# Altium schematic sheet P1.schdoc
size 594 x 419 mm; Symbol: Drawing-Symbol_A4; @Project Name: WYVERN-E; @Page Count: 1; @Update Date: 2026-08-05; @Create Date: 2026-08-05; @Schematic Name: Schematic1; @Page No: 1; @Page Name: P1; Company: EasyEDA.com; Version: V1.0; Page Size: A2; Device: Drawing-Symbol_A4; @Create Time: 14:42:15; @Update Time: 14:42:15; Border: 1; Width: 2338; Height: 1652; Region Start: 1; X Region Count: 6; Y Region Count: 4; Blade Width: 10; Title Block Position: 3; @Board Name: Board1
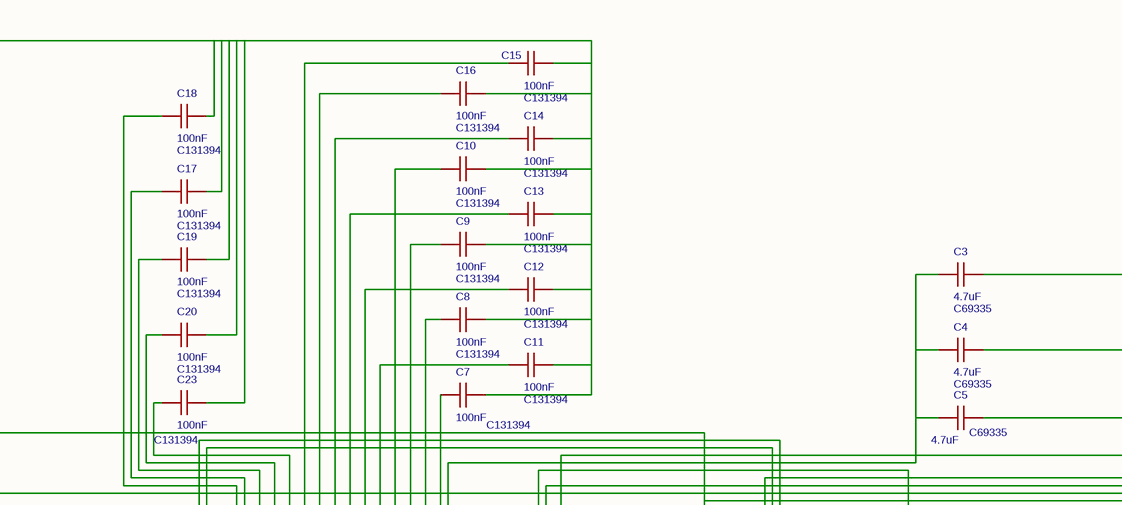
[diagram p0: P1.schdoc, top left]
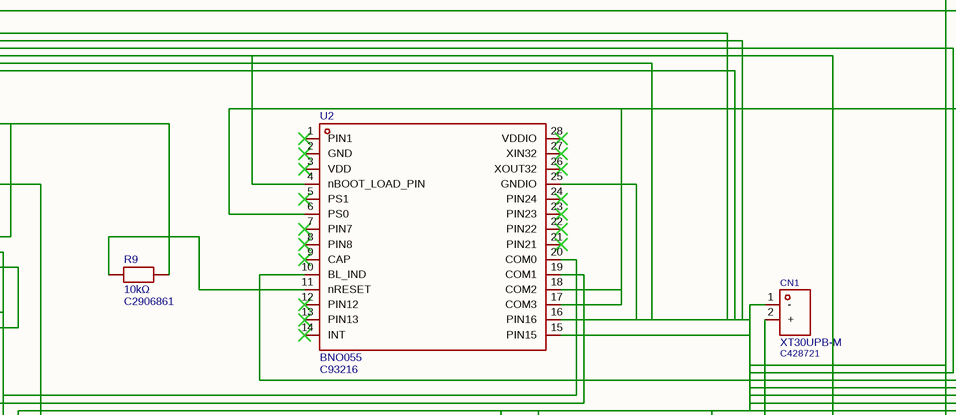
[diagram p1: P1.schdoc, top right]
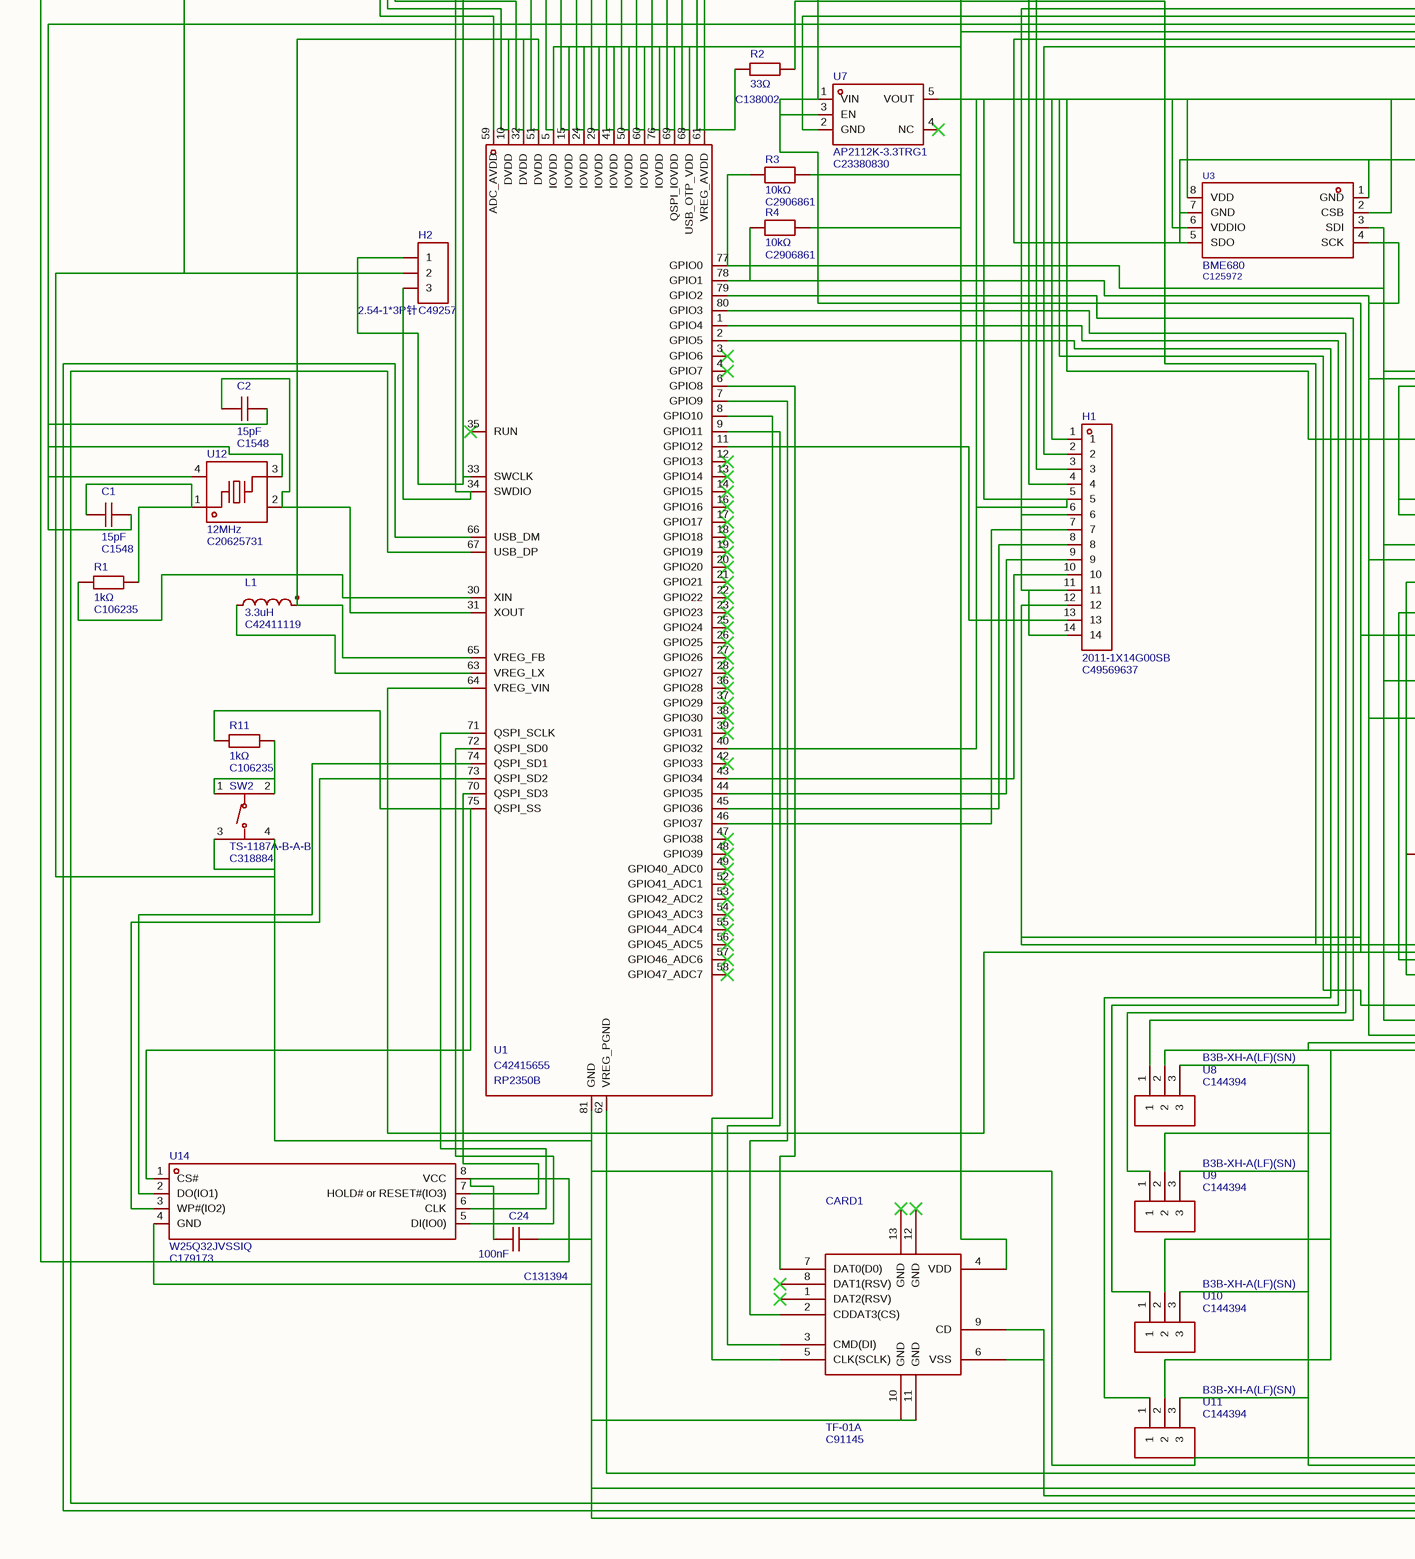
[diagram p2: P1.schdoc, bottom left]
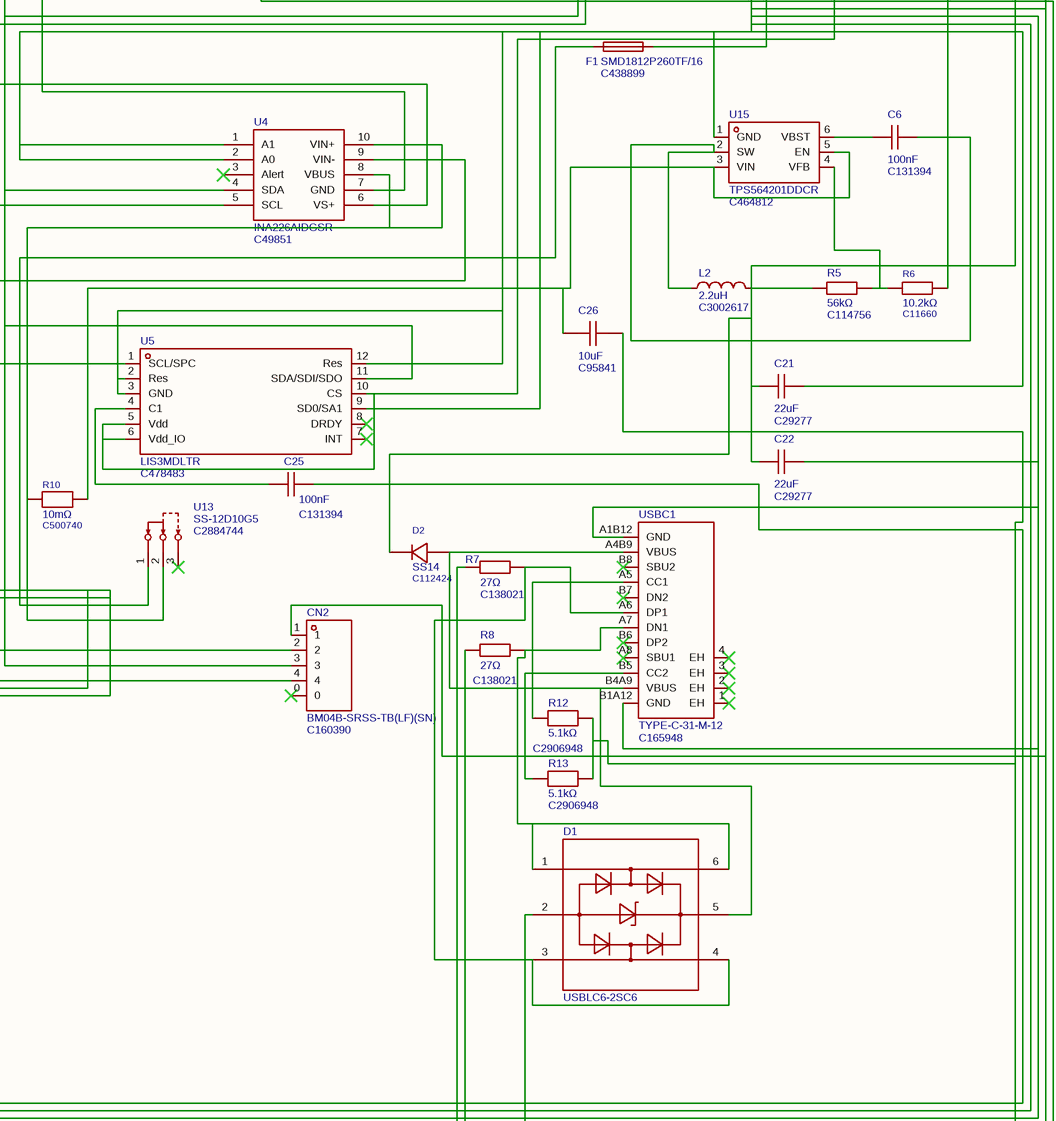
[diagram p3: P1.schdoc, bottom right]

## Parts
C1  15pF  Supplier Part: C1548  [C0402]
C2  15pF  Supplier Part: C1548  [C0402]
C3  4.7uF  Supplier Part: C69335  [C0603]
C4  4.7uF  Supplier Part: C69335  [C0603]
C5  4.7uF  Supplier Part: C69335  [C0603]
C6  100nF  Supplier Part: C131394  [C0402]
C7  100nF  Supplier Part: C131394  [C0402]
C8  100nF  Supplier Part: C131394  [C0402]
C9  100nF  Supplier Part: C131394  [C0402]
C10  100nF  Supplier Part: C131394  [C0402]
C11  100nF  Supplier Part: C131394  [C0402]
C12  100nF  Supplier Part: C131394  [C0402]
C13  100nF  Supplier Part: C131394  [C0402]
C14  100nF  Supplier Part: C131394  [C0402]
C15  100nF  Supplier Part: C131394  [C0402]
C16  100nF  Supplier Part: C131394  [C0402]
C17  100nF  Supplier Part: C131394  [C0402]
C18  100nF  Supplier Part: C131394  [C0402]
C19  100nF  Supplier Part: C131394  [C0402]
C20  100nF  Supplier Part: C131394  [C0402]
C21  22uF  Supplier Part: C29277  [C0805]
C22  22uF  Supplier Part: C29277  [C0805]
C23  100nF  Supplier Part: C131394  [C0402]
C24  100nF  Supplier Part: C131394  [C0402]
C25  100nF  Supplier Part: C131394  [C0402]
C26  10uF  Supplier Part: C95841  [C0805]
CARD1  TF-01A  Supplier Part: C91145  [TF-SMD_TF-01A]
CN1  XT30UPB-M  Supplier Part: C428721  [CONN-TH_XT30UPB-M]
CN2  BM04B-SRSS-TB(LF)(SN)  Supplier Part: C160390  [CONN-SMD_BM04B-SRSS-TB]
D1  USBLC6-2SC6  [SOT-23-6_L2.9-W1.6-P0.95-LS2.8-BL]
D2  SS14  Supplier Part: C112424  [SMA_L4.4-W2.6-LS5.0-RD]
F1  SMD1812P260TF/16  Supplier Part: C438899  [F1812]
H1  2011-1X14G00SB  Supplier Part: C49569637  [HDR-TH_14P-P2.54-V-M_4]
H2  2.54-1*3P针  Supplier Part: C49257  [HDR-TH_3P-P2.54-V-M-1]
L1  3.3uH  Supplier Part: C42411119  [IND-SMD_L2.0-W1.6_AOTA-B201610S3R3-101-T]
L2  2.2uH  Supplier Part: C3002617  [IND-SMD_L5.7-W5.1]
R1  1kΩ  Supplier Part: C106235  [R0402]
R2  33Ω  Supplier Part: C138002  [R0402]
R3  10kΩ  Supplier Part: C2906861  [R0402]
R4  10kΩ  Supplier Part: C2906861  [R0402]
R5  56kΩ  Supplier Part: C114756  [R0402]
R6  10.2kΩ  Supplier Part: C11660  [R0402]
R7  27Ω  Supplier Part: C138021  [R0402]
R8  27Ω  Supplier Part: C138021  [R0402]
R9  10kΩ  Supplier Part: C2906861  [R0402]
R10  10mΩ  Supplier Part: C500740  [R2512]
R11  1kΩ  Supplier Part: C106235  [R0402]
R12  5.1kΩ  Supplier Part: C2906948  [R0402]
R13  5.1kΩ  Supplier Part: C2906948  [R0402]
SW2  TS-1187A-B-A-B  Supplier Part: C318884  [SW-SMD_4P-L5.1-W5.1-P3.70-LS6.5-TL_H1.5]
U1  RP2350B  Supplier Part: C42415655  [QFN-80_L10.0-W10.0-P0.40-TL-EP3.4]
U2  BNO055  Supplier Part: C93216  [LGA-28_L5.2-W3.8-P0.50-BL]
U3  BME680  Supplier Part: C125972  [LGA-8_L3.0-W3.0-P0.80-TR]
U4  INA226AIDGSR  Supplier Part: C49851  [MSOP-10_L3.0-W3.0-P0.50-LS5.0-BL]
U5  LIS3MDLTR  Supplier Part: C478483  [LGA-12_L2.0-W2.0-P0.50-BL]
U7  AP2112K-3.3TRG1  Supplier Part: C23380830  [SOT-23-5_L2.9-W1.6-P0.95-LS2.8-BR]
U8  B3B-XH-A(LF)(SN)  Supplier Part: C144394  [CONN-TH_3P-P2.50_A2501WV2-3P]
U9  B3B-XH-A(LF)(SN)  Supplier Part: C144394  [CONN-TH_3P-P2.50_A2501WV2-3P]
U10  B3B-XH-A(LF)(SN)  Supplier Part: C144394  [CONN-TH_3P-P2.50_A2501WV2-3P]
U11  B3B-XH-A(LF)(SN)  Supplier Part: C144394  [CONN-TH_3P-P2.50_A2501WV2-3P]
U12  12MHz  Supplier Part: C20625731  [CRYSTAL-SMD_4P-L3.2-W2.5-BL]
U13  SS-12D10G5  Supplier Part: C2884744  [SW-TH_SS-12D10L9]
U14  W25Q32JVSSIQ  Supplier Part: C179173  [SOIC-8_L5.3-W5.3-P1.27-LS8.0-BL]
U15  TPS564201DDCR  Supplier Part: C464812  [SOT-23-6_L2.9-W1.6-P0.95-LS2.8-BL]
USBC1  TYPE-C-31-M-12  Supplier Part: C165948  [USB-C_SMD-TYPE-C-31-M-12_1]

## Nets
NetC1_1: C1.1 R1.2 U12.1
NetC1_2: C1.2 C2.2 C3.2 C4.2 C5.2 C7.2 C8.2 C9.2 C10.2 C11.2 C12.2 C13.2 C14.2 C15.2 C16.2 C17.2 C18.2 C19.2 C20.2 C21.2 C22.2 C23.2 C24.2 C25.2 C26.2 CARD1.6(VSS) CARD1.9(CD) CARD1.10(GND) CARD1.11(GND) CN1.1(-) CN2.1 D1.2 H1.2 H1.6 H1.11 H1.14 H2.2 R6.2 R12.2 R13.2 SW2.3(C) SW2.4(D) U1.62(VREG_PGND) U1.81(GND) U2.6(PS0) U2.10(BL_IND) U2.15(PIN15) U2.16(PIN16) U2.17(COM3) U2.18(COM2) U2.25(GNDIO) U3.1(GND) U3.5(SDO) U3.7(GND) U4.1(A1) U4.2(A0) U4.7(GND) U5.2(Res) U5.3(GND) U5.9(SD0/SA1) U5.12(Res) U7.2(GND) U8.3 U9.3 U10.3 U11.3 U12.3 U12.4(GND) U14.4(GND) U15.1(GND) USBC1.A1B12(GND) USBC1.B1A12(GND)
NetC2_1: C2.1 U1.31(XOUT) U12.2(GND)
NetC3_1: C3.1 C4.1 C5.1 C7.1 R2.1 U1.61(VREG_AVDD)
NetC6_1: C6.1 U15.6(VBST)
NetC6_2: C6.2 L2.1 U15.2(SW)
NetC8_1: C8.1 C9.1 C10.1 C11.1 C12.1 C13.1 C14.1 C15.1 C16.1 C23.1 C24.1 CARD1.4(VDD) CN2.2 H1.1 H1.5 R3.2 R4.2 R9.2 U1.5(IOVDD) U1.15(IOVDD) U1.24(IOVDD) U1.29(IOVDD) U1.40(GPIO32) U1.41(IOVDD) U1.50(IOVDD) U1.60(IOVDD) U1.68(USB_OTP_VDD) U1.69(QSPI_IOVDD) U1.76(IOVDD) U2.4(nBOOT_LOAD_PIN) U3.2(CSB) U3.6(VDDIO) U3.8(VDD) U4.6(VS+) U5.5(Vdd) U5.6(Vdd_IO) U5.10(CS) U7.5(VOUT) U14.8(VCC)
NetC17_1: C17.1 C19.1 C20.1 L1.2 U1.10(DVDD) U1.32(DVDD) U1.51(DVDD) U1.65(VREG_FB)
NetC18_1: C18.1 U1.59(ADC_AVDD)
NetC21_1: C21.1 C22.1 D2.1(C) H1.12 L2.2 R2.2 R5.1 U1.64(VREG_VIN) U4.9(VIN-) U7.1(VIN) U7.3(EN) U8.2 U9.2 U10.2 U11.2
NetC25_1: C25.1 U5.4(C1)
NetC26_1: C26.1 R10.2 U15.3(VIN) U15.5(EN)
NetCARD1_2: CARD1.2(CDDAT3(CS)) U1.7(GPIO9)
NetCARD1_3: CARD1.3(CMD(DI)) U1.9(GPIO11)
NetCARD1_5: CARD1.5(CLK(SCLK)) U1.8(GPIO10)
NetCARD1_7: CARD1.7(DAT0(D0)) U1.6(GPIO8)
NetCN1_2: CN1.2(+) F1.2
NetCN2_3: CN2.3 R3.1 U1.77(GPIO0) U2.20(COM0) U3.3(SDI) U4.4(SDA) U5.11(SDA/SDI/SDO)
NetCN2_4: CN2.4 R4.1 U1.78(GPIO1) U2.19(COM1) U3.4(SCK) U4.5(SCL) U5.1(SCL/SPC)
NetD1_1: D1.1 D1.6 R8.2 USBC1.A7(DN1)
NetD1_3: D1.3 D1.4 R7.2 USBC1.A6(DP1)
NetD1_5: D1.5 D2.2(A) USBC1.A4B9(VBUS) USBC1.B4A9(VBUS)
NetF1_1: F1.1 U13.1
NetH1_3: H1.3 H2.3 U1.34(SWDIO)
NetH1_4: H1.4 H2.1 U1.33(SWCLK)
NetH1_7: H1.7 U1.46(GPIO37)
NetH1_8: H1.8 U1.45(GPIO36)
NetH1_9: H1.9 U1.44(GPIO35)
NetH1_10: H1.10 U1.43(GPIO34)
NetH1_13: H1.13 U1.11(GPIO12)
NetL1_1: L1.1 U1.63(VREG_LX)
NetR1_1: R1.1 U1.30(XIN)
NetR5_2: R5.2 R6.1 U15.4(VFB)
NetR7_1: R7.1 U1.67(USB_DP)
NetR8_1: R8.1 U1.66(USB_DM)
NetR9_1: R9.1 U2.11(nRESET)
NetR10_1: R10.1 U4.8(VBUS) U4.10(VIN+) U13.2
NetR11_1: R11.1 U1.75(QSPI_SS) U14.1(CS#)
NetR11_2: R11.2 SW2.1(A) SW2.2(B)
NetR12_1: R12.1 USBC1.A5(CC1)
NetR13_1: R13.1 USBC1.B5(CC2)
NetU1_1: U1.1(GPIO4) U10.1
NetU1_2: U1.2(GPIO5) U11.1
NetU1_70: U1.70(QSPI_SD3) U14.7(HOLD#_or_RESET#(IO3))
NetU1_71: U1.71(QSPI_SCLK) U14.6(CLK)
NetU1_72: U1.72(QSPI_SD0) U14.5(DI(IO0))
NetU1_73: U1.73(QSPI_SD2) U14.3(WP#(IO2))
NetU1_74: U1.74(QSPI_SD1) U14.2(DO(IO1))
NetU1_79: U1.79(GPIO2) U8.1
NetU1_80: U1.80(GPIO3) U9.1

Not connected (* = marked no-connect by the designer): CARD1 1(DAT2(RSV))* 8(DAT1(RSV))* 12(GND)* 13(GND)*; CN2 0*; U1 3(GPIO6)* 4(GPIO7)* 12(GPIO13)* 13(GPIO14)* 14(GPIO15)* 16(GPIO16)* 17(GPIO17)* 18(GPIO18)* 19(GPIO19)* 20(GPIO20)* 21(GPIO21)* 22(GPIO22)* 23(GPIO23)* 25(GPIO24)* 26(GPIO25)* 27(GPIO26)* 28(GPIO27)* 35(RUN)* 36(GPIO28)* 37(GPIO29)* 38(GPIO30)* 39(GPIO31)* 42(GPIO33)* 47(GPIO38)* 48(GPIO39)* 49(GPIO40_ADC0)* 52(GPIO41_ADC1)* 53(GPIO42_ADC2)* 54(GPIO43_ADC3)* 55(GPIO44_ADC4)* 56(GPIO45_ADC5)* 57(GPIO46_ADC6)* 58(GPIO47_ADC7)*; U2 1(PIN1)* 2(GND)* 3(VDD)* 5(PS1)* 7(PIN7)* 8(PIN8)* 9(CAP)* 12(PIN12)* 13(PIN13)* 14(INT)* 21(PIN21)* 22(PIN22)* 23(PIN23)* 24(PIN24)* 26(XOUT32)* 27(XIN32)* 28(VDDIO)*; U4 3(Alert)*; U5 7(INT)* 8(DRDY)*; U7 4(NC)*; U13 3*; USBC1 1(EH)* 2(EH)* 3(EH)* 4(EH)* A8(SBU1)* B6(DP2)* B7(DN2)* B8(SBU2)*

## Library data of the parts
C1 C2 = 0402CG150J500NT: Capacitance:15pF Tolerance:±5% Tolerance:±5% Voltage Rating:50V Temperature Coefficient:C0G; Manufacturer: FH(风华); AddInBom: yes; ModelId: b7d13df3e9464d7a99d0651d1a5b4d570819f05c4eef4c71ace90d822a990e87; ModelName: C0402_L1.0-W0.5-H0.5; ModelTransform: 39.37,19.685,0,0,0,0,0,0,0; Tolerance: ±5%; Voltage Rating: 50V; Temperature Coefficient: C0G
C3-C5 = CL10A475KA8NQNC: Capacitance:4.7uF Tolerance:±10% Tolerance:±10% Voltage Rating:25V Temperature Coefficient:X5R; Manufacturer: SAMSUNG(三星); 3D Model: 624118aa3cc7497086c383c2d72e08520819f05c4eef4c71ace90d822a990e87; 3D Model Transform: 62.992,31.496,0,0,0,0,0,0,0; Tolerance: ±10%; Voltage Rating: 25V; Temperature Coefficient: X5R; AddInBom: yes; ModelName: C0603_L1.6-W0.8-H0.8
C6 = CC0402KRX7R9BB104: Capacitance:100nF Tolerance:±10% Tolerance:±10% Voltage Rating:50V Temperature Coefficient:X7R; Manufacturer: YAGEO(国巨); AddInBom: yes; ModelId: b7d13df3e9464d7a99d0651d1a5b4d570819f05c4eef4c71ace90d822a990e87; ModelName: C0402_L1.0-W0.5-H0.5; ModelTransform: 39.37,19.685,0,0,0,0,0,0,0; Tolerance: ±10%; Voltage Rating: 50V; Temperature Coefficient: X7R
C7-C20 C23-C25 = CC0402KRX7R9BB104: Capacitance:100nF Tolerance:±10% Tolerance:±10% Voltage Rating:50V Temperature Coefficient:X7R; Manufacturer: YAGEO(国巨); 3D Model: b7d13df3e9464d7a99d0651d1a5b4d570819f05c4eef4c71ace90d822a990e87; 3D Model Transform: 39.37,19.685,0,0,0,0,0,0,0; Tolerance: ±10%; Voltage Rating: 50V; Temperature Coefficient: X7R; AddInBom: yes; ModelName: C0402_L1.0-W0.5-H0.5
C21 C22 = CL21A226MPQNNNE: Capacitance:22uF Tolerance:±20% Tolerance:±20% Voltage Rating:10V Temperature Coefficient:X5R; Manufacturer: SAMSUNG(三星); AddInBom: yes; ModelId: 8c88e81f49c6409b980720ec8953afb60819f05c4eef4c71ace90d822a990e87; ModelName: C0805_L2.0-W1.3-H1.3; ModelTransform: 78.74,51.181,0,0,0,0,0,0.0005,0; Tolerance: ±20%; Voltage Rating: 10V; Temperature Coefficient: X5R
C26 = CL21B106KOQNNNE: Capacitance:10uF Tolerance:±10% Tolerance:±10% Voltage Rating:16V Temperature Coefficient:X7R; Manufacturer: SAMSUNG(三星); AddInBom: yes; ModelId: 8c88e81f49c6409b980720ec8953afb60819f05c4eef4c71ace90d822a990e87; ModelName: C0805_L2.0-W1.3-H1.3; ModelTransform: 78.74,51.181,0,0,0,0,0,0.0005,0; Tolerance: ±10%; Voltage Rating: 16V; Temperature Coefficient: X7R
CARD1 = TF-01A_C91145: Card Connection Mode:Push-Push Card Type:MicroSD Card (TF Card) Connector Type:Connector and Ejector Additional Card Detection Pins:- Supplementary Features:With Locating Pins Height Above Board:1.85mm Operating Temperature:- Operating Temperature:-; Manufacturer: 韩国韩荣; 3D Model: 5685a23adc9a4e3e9b914abe5ae03aae0819f05c4eef4c71ace90d822a990e87; 3D Model Transform: 633.85696,590.65303,0,0,0,0,0,-85.63,-23.622; AddInBom: yes
CN1 = XT30UPB-M: Rated current:15A Rated voltage: colour:Yellow Connector type:Model aircraft plug contact resistance: interface form:Male insulating material: metal material:Gold plating; Manufacturer: AMASS(艾迈斯); 3D Model: 8606296c6a2a4a0aa30f28b26a2c1e3a0819f05c4eef4c71ace90d822a990e87; 3D Model Transform: 401.574,204.724,0,0,0,0,0,0,-78.74; Rated current: 15A; interface form: Male; AddInBom: yes
CN2 = BM04B-SRSS-TB(LF)(SN): Pins Structure:1x4P Pitch:1mm Mounting Type:Surface Mount,Vertical Reference Series:SR Number of Pins:4P Number of Rows:1 Number of PINs Per Row:4 Row Spacing:- Current Rating:1A Contact Material:Copper alloy Contact Plating:Tin Operating Temperature:-25℃; Manufacturer: JST; AddInBom: yes; ModelId: c8b0a6165d564a1890ab3ee4bf911cf30819f05c4eef4c71ace90d822a990e87; ModelName: CONN-SMD_4P-L6.0-W2.9-H4.3-P1.0; ModelTransform: 236.22,142.1257,0,0,0,0,0,5.906,0; Pins Structure: 1x4P; Pitch: 1mm; Reference Series: SR; Number of PINs Per Row: 4; Current Rating: 1A; Voltage Rating: 50V; Plastic Material: PA; Flame Retardant Rating: UL94V-0; Supplementary Features: Auxiliary Solder Pin; Z-Height of the Board: 4.25mm; X-Length of Bottom Edge on Board (Spacing Line): 6mm; Y-Width of Bottom Edge on Board: 3.6mm
D1 = USBLC6-2SC6_C7519: Polarity:Unidirectional Reverse Stand-Off Voltage (Vrwm):5.25V Clamping Voltage:17V Peak Pulse Current (Ipp):5A Voltage - Breakdown:6V Reverse Leakage Current (Ir):150nA Number of Channels:2 Operating Temperature:-40℃~+125℃ Operating Temperature:-40℃~+125; Manufacturer: ST(意法半导体); AddInBom: yes; ModelId: 1370be37a17e44418ae52e2b4cc1f5e50819f05c4eef4c71ace90d822a990e87; ModelName: SOT-23-6_L2.9-W1.6-H1.5-LS2.8-P0.95; ModelTransform: 110.236,113.364,0,90,0,0,0.0005,0.0005,0; Reverse Stand-Off Voltage (Vrwm): 5.25V; Clamping Voltage: 17V; Peak Pulse Current (Ipp): 5A; Voltage - Breakdown: 6V; Reverse Leakage Current (Ir): 150nA; Number of Channels: 2; level of protection: IEC 61000-4-2; Type: ESD; Junction Capacitance: 3.5pF
D2 = SS14_C112424: Voltage - Forward(Vf@If):550mV@1A Voltage - DC Reverse(Vr):40V Current - Rectified:1A Reverse Leakage Current (Ir):300uA@40V Operating Junction Temperature Range:-55℃~+125℃ Operating Junction Temperature Range:-55℃~+125℃ Non-Repetitive Peak Forward Surge; Manufacturer: 晶导微电子; AddInBom: yes; ModelId: f51095f10bda4868a97202a5ed5885410819f05c4eef4c71ace90d822a990e87; ModelTransform: 204.724,98.425,0,0,0,0,0,0,0; Voltage - DC Reverse(Vr): 40V; Current - Rectified: 1A; Non-Repetitive Peak Forward Surge Current: 30A
F1 = SMD1812P260TF/16_C438899: Voltage - Max:16V Current - Max:100A Hold Current:2.6A Trip Current:5A Power Dissipation:1.2W Resistance - Initial (Ri) (Min):15mΩ Resistance - Post Trip (R1) (Max):50mΩ Time to Trip(Max):5s Operating Temperature:-40℃~+85℃ Operating Temperature:-40℃~+85℃; Manufacturer: PTTC(聚鼎); AddInBom: yes; ModelId: 2c21fc2ee1444accbf1837c83de544380819f05c4eef4c71ace90d822a990e87; ModelName: F1812_L4.5-W3.2-H1.0; ModelTransform: 177.165,125.984,0,0,0,0,0.0005,0,0; Voltage - Max: 16V; Current - Max: 100A; Hold Current: 2.6A; Trip Current: 5A; Power Dissipation: 1.2W; Resistance - Initial (Ri) (Min): 15mΩ; Resistance - Post Trip (R1) (Max): 50mΩ; Time to Trip(Max): 5s
H1 = 2011-1X14G00SB: Pin Structure:1x14P Pitch:2.54mm Circluar Pins/Square Pins:Pin Header Mounting Type:Through Hole Number of Rows:1 Number of Pins:14P Current Rating:3A Voltage Rating (Max):600V Length of Mating Pin:6mm Insulation Height:2.5mm Length of End Connection Pin:; Manufacturer: WingTAT(格林柏); 3D Model: f6b8b1151f3d4858b245f95bf957bfbf0819f05c4eef4c71ace90d822a990e87; 3D Model Transform: 1399.997,98.8187,0,0,0,0,0,0,-118.11; Pin Structure: 1x14P; Pitch: 2.54mm; Current Rating: 3A; Voltage Rating (Max): 600V; AddInBom: yes
H2 = 2.54-1*3P针: Pin Structure:1x3P Pitch:2.54mm Row Spacing:- Circluar Pins/Square Pins:Pin Header Mounting Type:Through Hole Number of Rows:1 Number of Pins:3P Current Rating:3A Voltage Rating (Max):- Length of Mating Pin:6mm Insulation Height:2.5mm Length of End Connec; Manufacturer: BOOMELE(博穆精密); Symbol: Header-Male-2.54_1x3; AddInBom: yes; ModelId: 3b8cf4ff435f4f2b912293f2932d05980819f05c4eef4c71ace90d822a990e87; ModelName: HDR-M-2.54_1x3; ModelTransform: 299.9994,100,0,0,0,0,0,0,-118.11; Pin Structure: 1x3P; Pitch: 2.54mm; Current Rating: 3A
L1 = AOTA-B201610S3R3-101-T: Inductance:3.3uH Current Rating:2.1A Current - Saturation(Isat):2.4A DC Resistance(DCR):115mΩ Type:Molded Inductor; Manufacturer: ABRACON; AddInBom: yes; ModelId: 1fea8f9ef5b64dc68dc98052e0860c3b0819f05c4eef4c71ace90d822a990e87; ModelTransform: 78.74,63.3857,0,0,0,0,0,0,0; Current Rating: 2.1A; Current - Saturation(Isat): 2.4A; DC Resistance(DCR): 115mΩ
L2 = CKST0503-2.2uH/M: Inductance:2.2uH Tolerance:±20% Tolerance:±20% Current Rating:5.5A Current - Saturation(Isat):8A DC Resistance(DCR):35mΩ Type:Molded Inductor; Manufacturer: CENKER(岑科); AddInBom: yes; ModelId: d24c9350d8104ec89ed3aa7259e95cc50819f05c4eef4c71ace90d822a990e87; ModelTransform: 224.409,200.787,0,0,0,0,0,-0.591,0; Tolerance: ±20%; Current Rating: 5.5A; Current - Saturation(Isat): 8A; DC Resistance(DCR): 35mΩ
R1 = RC0402FR-071KL: Type:Thick Film Resistor Resistance:1kΩ Tolerance:±1% Tolerance:±1% Power(Watts):62.5mW Voltage-Supply(Max):50V Temperature Coefficient:±100ppm/℃ Temperature Coefficient:±100ppm/℃ Operating Temperature:-55℃~+155℃ Operating Temperature:-55℃~+155℃; Manufacturer: YAGEO(国巨); AddInBom: yes; ModelId: efdecb7dae4442949d28eecaf748420f0819f05c4eef4c71ace90d822a990e87; ModelName: R0402_L1.0-W0.5-H0.4; ModelTransform: 39.37,19.685,0,0,0,0,0,0,0; Tolerance: ±1%; Power(Watts): 62.5mW; Voltage-Supply(Max): 50V
R2 = RC0402FR-0733RL: Type:Thick Film Resistor Resistance:33Ω Tolerance:±1% Tolerance:±1% Power(Watts):62.5mW Voltage-Supply(Max):50V Temperature Coefficient:±100ppm/℃ Temperature Coefficient:±100ppm/℃ Operating Temperature:-55℃~+155℃ Operating Temperature:-55℃~+155℃; Manufacturer: YAGEO(国巨); AddInBom: yes; ModelId: efdecb7dae4442949d28eecaf748420f0819f05c4eef4c71ace90d822a990e87; ModelName: R0402_L1.0-W0.5-H0.4; ModelTransform: 39.37,19.685,0,0,0,0,0,0,0; Tolerance: ±1%; Power(Watts): 62.5mW; Voltage-Supply(Max): 50V
R3 R4 R9 = FRC0402F1002TS: Type:Thick Film Resistor Resistance:10kΩ Tolerance:±1% Tolerance:±1% Power(Watts):62.5mW Voltage-Supply(Max):50V Temperature Coefficient:±100ppm/℃ Temperature Coefficient:±100ppm/℃ Operating Temperature:-55℃~+155℃ Operating Temperature:-55℃~+155℃; Manufacturer: FOJAN(富捷); 3D Model: efdecb7dae4442949d28eecaf748420f0819f05c4eef4c71ace90d822a990e87; 3D Model Transform: 39.37,19.685,0,0,0,0,0,0,0; Tolerance: ±1%; Power(Watts): 62.5mW; Voltage-Supply(Max): 50V; AddInBom: yes; ModelName: R0402_L1.0-W0.5-H0.4
R5 = RC0402FR-0756KL: Type:Thick Film Resistor Resistance:56kΩ Tolerance:±1% Tolerance:±1% Power(Watts):62.5mW Voltage-Supply(Max):50V Temperature Coefficient:±100ppm/℃ Temperature Coefficient:±100ppm/℃ Operating Temperature:-55℃~+155℃ Operating Temperature:-55℃~+155℃; Manufacturer: YAGEO(国巨); AddInBom: yes; ModelId: efdecb7dae4442949d28eecaf748420f0819f05c4eef4c71ace90d822a990e87; ModelName: R0402_L1.0-W0.5-H0.4; ModelTransform: 39.37,19.685,0,0,0,0,0,0,0; Tolerance: ±1%; Power(Watts): 62.5mW; Voltage-Supply(Max): 50V
R6 = 0402WGF1022TCE: Type:Thick Film Resistor Resistance:10.2kΩ Tolerance:±1% Tolerance:±1% Power(Watts):62.5mW Voltage-Supply(Max):50V Temperature Coefficient:±100ppm/℃ Temperature Coefficient:±100ppm/℃ Operating Temperature:-55℃~+155℃ Operating Temperature:-55℃~+155℃; Manufacturer: UNI-ROYAL(厚声); AddInBom: yes; ModelId: efdecb7dae4442949d28eecaf748420f0819f05c4eef4c71ace90d822a990e87; ModelName: R0402_L1.0-W0.5-H0.4; ModelTransform: 39.37,19.685,0,0,0,0,0,0,0; Tolerance: ±1%; Power(Watts): 62.5mW; Voltage-Supply(Max): 50V
R7 R8 = RC0402FR-0727RL: Type:Thick Film Resistor Resistance:27Ω Tolerance:±1% Tolerance:±1% Power(Watts):62.5mW Voltage-Supply(Max):50V Temperature Coefficient:±100ppm/℃ Temperature Coefficient:±100ppm/℃ Operating Temperature:-55℃~+155℃ Operating Temperature:-55℃~+155℃; Manufacturer: YAGEO(国巨); AddInBom: yes; ModelId: efdecb7dae4442949d28eecaf748420f0819f05c4eef4c71ace90d822a990e87; ModelName: R0402_L1.0-W0.5-H0.4; ModelTransform: 39.37,19.685,0,0,0,0,0,0,0; Tolerance: ±1%; Power(Watts): 62.5mW; Voltage-Supply(Max): 50V
R10 = LR2512DS-3W-10mR-1%: Type:Current Sensing Resistors Resistance:10mΩ Tolerance:±1% Tolerance:±1% Power(Watts): Temperature Coefficient:±25ppm/℃ Temperature Coefficient:±25ppm/℃ Mounting Sytle:Surface Mount; Manufacturer: Milliohm(毫欧); AddInBom: yes; ModelId: c704f12ea0da45b6b9e7d0ddac98e7f70819f05c4eef4c71ace90d822a990e87; ModelName: R2512_L6.3-W3.2-H0.6; ModelTransform: 248.031,125.984,0,0,0,0,-0.0005,0,0; Tolerance: ±1%
R11 = RC0402FR-071KL: Type:Thick Film Resistor Resistance:1kΩ Tolerance:±1% Tolerance:±1% Power(Watts):62.5mW Voltage-Supply(Max):50V Temperature Coefficient:±100ppm/℃ Temperature Coefficient:±100ppm/℃ Operating Temperature:-55℃~+155℃ Operating Temperature:-55℃~+155℃; Manufacturer: YAGEO(国巨); 3D Model: efdecb7dae4442949d28eecaf748420f0819f05c4eef4c71ace90d822a990e87; 3D Model Transform: 39.37,19.685,0,0,0,0,0,0,0; Tolerance: ±1%; Power(Watts): 62.5mW; Voltage-Supply(Max): 50V; AddInBom: yes; ModelName: R0402_L1.0-W0.5-H0.4
R12 = FRC0402J512 TS: Type:Thick Film Resistor Resistance:5.1kΩ Tolerance:±5% Tolerance:±5% Power(Watts):62.5mW Voltage-Supply(Max):50V Temperature Coefficient:±100ppm/℃ Temperature Coefficient:±100ppm/℃ Operating Temperature:-55℃~+155℃ Operating Temperature:-55℃~+155℃; Manufacturer: FOJAN(富捷); AddInBom: yes; ModelId: efdecb7dae4442949d28eecaf748420f0819f05c4eef4c71ace90d822a990e87; ModelName: R0402_L1.0-W0.5-H0.4; ModelTransform: 39.37,19.685,0,0,0,0,0,0,0; Tolerance: ±5%; Power(Watts): 62.5mW; Voltage-Supply(Max): 50V
R13 = FRC0402J512 TS: Type:Thick Film Resistor Resistance:5.1kΩ Tolerance:±5% Tolerance:±5% Power(Watts):62.5mW Voltage-Supply(Max):50V Temperature Coefficient:±100ppm/℃ Temperature Coefficient:±100ppm/℃ Operating Temperature:-55℃~+155℃ Operating Temperature:-55℃~+155℃; Manufacturer: FOJAN(富捷); 3D Model: efdecb7dae4442949d28eecaf748420f0819f05c4eef4c71ace90d822a990e87; 3D Model Transform: 39.37,19.685,0,0,0,0,0,0,0; Tolerance: ±5%; Power(Watts): 62.5mW; Voltage-Supply(Max): 50V; AddInBom: yes; ModelName: R0402_L1.0-W0.5-H0.4
SW2 = TS-1187A-B-A-B: Circuit:SPST Actuator Style:Round Button Operating Force:1.6N Mounting Type:Surface Mount,Vertical Length:5.1mm Width:5.1mm Switch Height:1.5mm with Bracket:Without Bracket Contact Current:50mA Voltage Rating:12V Actuator/Cap Color:Gold With Lamp:No Life:; Manufacturer: XKB Connection(中国星坤); AddInBom: yes; ModelId: 297e93217c8a461096f3cf9cc3d4db3d0819f05c4eef4c71ace90d822a990e87; ModelTransform: 255.905,204.76337,0,0,0,0,0,0,0; Circuit: SPST; Operating Force: 1.6N; Switch Height: 1.5mm; Contact Current: 50mA; Voltage Rating: 12V; Actuator/Cap Color: Gold; With Lamp: No; Life: 100,000 cycles
U1 = RP2350B_C42415655: Number of I/O:48 Features:Independent watchdog (IWDG)；Power-on reset (POR)；True random number generator (TRNG)；Watchdog reset；Built-in general-purpose timer；Hardware ECC check；External pin reset (NRST)；Integrated LDO; Manufacturer: Raspberry Pi(树莓派); Add into BOM: yes; 3D Model: 9f007f8a42644ad5aa4c6524189812eb0819f05c4eef4c71ace90d822a990e87; 3D Model Transform: 394.487,394.487,0,0,0,0,0,0,0; Number of I/O: 48
U2 = BNO055: Accelerometer Sensing Axis:X,Y,Z Acceleration Measurement Range (MAX):±16g Acceleration Measurement Range (MAX):±16g Gyroscope Sensing Axis:X,Y,Z Gyroscope Measurement Range (MAX):±2000dps Gyroscope Measurement Range (MAX):±2000dps Sensor Type:IMU (accele; Manufacturer: Bosch(博世); 3D Model: 2256a7a8c01e4b8c876389a77bde68f70819f05c4eef4c71ace90d822a990e87; 3D Model Transform: 204.724,149.606,0,90,0,0,-0.004,0.004,0; Accelerometer Sensing Axis: X,Y,Z; Acceleration Measurement Range (MAX): ±16g; Sensor Type: IMU (accelerometer + gyroscope); Output Bits: 14bit；16bit; Interface: UART；I2C; Voltage - Supply: 2.4V~3.6V; Standby Current: 40uA; AddInBom: yes; ModelName: LGA-28_L5.2-W3.8-H1.2-P0.50-BL
U3 = BME680: Pressure range:30Kpa~1.1bar Pressure range:30Kpa~1.1bar Voltage - Supply:1.71V~3.6V Voltage - Supply:1.71V~3.6V Standby Current:150nA Interface:SPI；I2C Module:- Absolute Accuracy:0.6hpa Relative Accuracy:0.12hpa Features:Standby mode；Integrated ADC and di; Manufacturer: Bosch(博世); 3D Model: b8c5a93640fd43cf889b444887718f200819f05c4eef4c71ace90d822a990e87; 3D Model Transform: 118.11,118.11,0,0,0,0,0,0,0; Standby Current: 150nA; Absolute Accuracy: 0.6hpa; Temperature Coefficient of Offset(TCO): 1.3pa/K; AddInBom: yes; ModelName: LGA-8_L3.0-W3.0-H0.9-P0.80-TR
U4 = INA226AIDGSR: Number of Channels:- Vcm - Common Mode Voltage:0V~36V Vcm - Common Mode Voltage:0V~36V Gain:- Bandwidth:- Ib - Input Bias Current:100pA Vos - Input Offset Voltage:2.5uV Operating Temperature:-40℃~+125℃ Operating Temperature:-40℃~+125℃ Differential Voltage; Manufacturer: TI(德州仪器); 3D Model: 875cf331c88d40d1aea94374997f39b10819f05c4eef4c71ace90d822a990e87; 3D Model Transform: 118.11,196.85,0,0,0,0,0,0,0; Vcm - Common Mode Voltage: 0V~36V; Ib - Input Bias Current: 100pA; Vos - Input Offset Voltage: 2.5uV; Differential Voltage: ±40V; Single Supply: 2.7V~5.5V; Quiescent Current: 330uA; Input Offset Voltage Drift(Vos TC): 0.1uV/℃; Common Mode Rejection Ratio (CMRR): 140dB; AddInBom: yes; ModelName: MSOP-10_L3.0-W3.0-H1.1-LS5.0-P0.50
U5 = LIS3MDLTR: Magnetic Sensing Range(X,Y):±1.2mT；±1.6mT；±4Gs；±8Gs Magnetic Sensing Range(X,Y):±1.2mT；±1.6mT；±4Gs；±8Gs Magnetic Sensing Range(Z):±4Gs；±1.2mT；±8Gs；±1.6mT Magnetic Sensing Range(Z):±4Gs；±1.2mT；±8Gs；±1.6mT Output bit:16bit Interface Type:SPI；I2C Voltage - S; Manufacturer: ST(意法半导体); 3D Model: 08d0e00f89c34818888f739e33f114130819f05c4eef4c71ace90d822a990e87; 3D Model Transform: 78.74,78.74,0,90,0,0,0,0.001,0; Output bit: 16bit; Voltage - Supply: 1.9V~3.6V; Current - Supply: 270uA；1uA；40uA; AddInBom: yes; ModelName: LGA-12_L2.0-W2.0-H1.0-P0.50
U7 = AP2112K-3.3TRG1_C23380830: Output Configuration:Positive Voltage - Supply:5.5V Output Voltage:3.3V Output Voltage:3.3V Output Current:600mA Power Supply Rejection Ratio (PSRR):75dB@(1kHz) Voltage Dropout:320mV@(600mA) standby current:10uA Noise:- Features:Enable control；Over Curren; Manufacturer: TECH PUBLIC(台舟); AddInBom: yes; ModelId: 5bf53fa97d9848eeb37d584d4730b7f10819f05c4eef4c71ace90d822a990e87; ModelTransform: 114.173,114.173,0,90,0,0,0,0,0; Voltage - Supply: 5.5V; Output Voltage: 3.3V; standby current: 10uA; Output Type: Fixed; Number of Outputs: 1
U8-U11 = B3B-XH-A(LF)(SN): Pins Structure:1x3P Pitch:2.5mm Mounting Type:Through Hole Reference Series:XH Number of Pins:3P Number of Rows:1 Number of PINs Per Row:3 Row Spacing:- Current Rating:3A Contact Material:Brass Contact Plating:Tin Operating Temperature:-25℃~+85℃ Operating; Manufacturer: JST; 3D Model: 5bef03a823d44d6d8bbe2419212192340819f05c4eef4c71ace90d822a990e87; 3D Model Transform: 393.7,226.3775,0,0,0,0,-0.005,-18.465,-125.984; Pins Structure: 1x3P; Pitch: 2.5mm; Reference Series: XH; Number of PINs Per Row: 3; Current Rating: 3A; Voltage Rating: 250V; Plastic Material: PA66; Flame Retardant Rating: UL94V-0; Supplementary Features: K Pin; Z-Height of the Board: 7mm; X-Length of Bottom Edge on Board (Spacing Line): 9.9mm; Y-Width of Bottom Edge on Board: 5.75mm; AddInBom: yes
U12 = ABM8-272-T3_C20625731: Type:Crystal Oscillator Frequency:12MHz Normal temperature Frequency Tolerance:±30ppm Normal temperature Frequency Tolerance:±30ppm Load Capacitance:10pF Frequency Stability:±30ppm Frequency Stability:±30ppm Equivalent Series Resistance(ESR):50Ω Operating; Manufacturer: ABRACON; AddInBom: yes; ModelId: a2b47bc5d32f4dfd996128e047b549a00819f05c4eef4c71ace90d822a990e87; ModelTransform: 125.984,98.425,0,0,0,0,0,0,0; Normal temperature Frequency Tolerance: ±30ppm; Load Capacitance: 10pF; Equivalent Series Resistance(ESR): 50Ω
U13 = SS-12D10G5: Circuit:SPDT Actuator Style:Rectangular Columnar Termination Style:PC Pin Length:- Width:- Switch Height:- Mounting Type:Through Hole Actuator Color:Black Current Rating:- Voltage Rating:125V Life:10000 times Operating Temperature:-40℃~+85℃ Operating Temp; Manufacturer: XKB Connection(中国星坤); AddInBom: yes; ModelId: d2ded76b0d42481fbf8bdb9ee36841400819f05c4eef4c71ace90d822a990e87; ModelTransform: 511.81,291.338,0,0,0,0,0,0,-236.22; Circuit: SPDT; Actuator Color: Black; Voltage Rating: 125V
U14 = W25Q32JVSSIQ: Interface:SPI Memory Size:32Mbit Clock Frequency:133MHz Voltage - Supply:2.7V~3.6V Voltage - Supply:2.7V~3.6V Standby Supply Current:1uA Program / Erase Cycles:100,000 cycles Write Cycle Time (tWC):- Page Programming Time (Tpp):3ms Block Erase Time(tBE):-; Manufacturer: Winbond(华邦); Symbol: W25Q32JVSSIQ_C179173; AddInBom: yes; ModelId: 7b3104f4a302484e875593c5ba7bd3db0819f05c4eef4c71ace90d822a990e87; ModelName: SOIC-8_L5.3-W5.3-H1.9-LS7.9-P1.27; ModelTransform: 208.661,311.25654,0,0,0,0,-0.0005,0.0005,0; Interface: SPI; Memory Size: 32Mbit; Clock Frequency: 133MHz; Standby Supply Current: 1uA; Page Programming Time (Tpp): 3ms; Data Retention - TDR (Year): 20 Years
U15 = TPS564201DDCR: Function:Step-down type Voltage - Supply:4.5V~17V Voltage - Supply:4.5V~17V Output Voltage:760mV~7V Output Voltage:760mV~7V Output Current:4A Frequency - Switching:560kHz Frequency - Switching:560kHz Operating Temperature:-40℃~+125℃@(TJ) Operating Tempera; Manufacturer: TI(德州仪器); AddInBom: yes; ModelId: 1370be37a17e44418ae52e2b4cc1f5e50819f05c4eef4c71ace90d822a990e87; ModelName: SOT-23-6_L2.9-W1.6-H1.5-LS2.8-P0.95; ModelTransform: 110.236,113.364,0,90,0,0,0.0005,0.0005,0; Output Current: 4A; Frequency - Switching: 560kHz; Number of Outputs: 1; Topology: Buck; Quiescent Current: 510uA; Switch tube (built-in/external): Built-in; Output Type: Adjustable
USBC1 = TYPE-C-31-M-12: Connector Type:Type-C Protocol Standard:- Gender:Female Mounting Type:Surface Mount, Right Angle Number of Contacts:16P Number of Ports:1 Current Rating-Power:5A Voltage Rating:20V Connect-Disconnect Life:10,000 cycles Length:7.35mm Operating Temperature:; Manufacturer: 韩国韩荣; 3D Model: 8421221a464047838322348b3a9debc30819f05c4eef4c71ace90d822a990e87; 3D Model Transform: 351.9678,311.023,0,180,0,0,0,-43.307,-33.465; Connector Type: Type-C; Gender: Female; Number of Contacts: 16P; Number of Ports: 1; Current Rating-Power: 5A; Voltage Rating: 20V; AddInBom: yes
